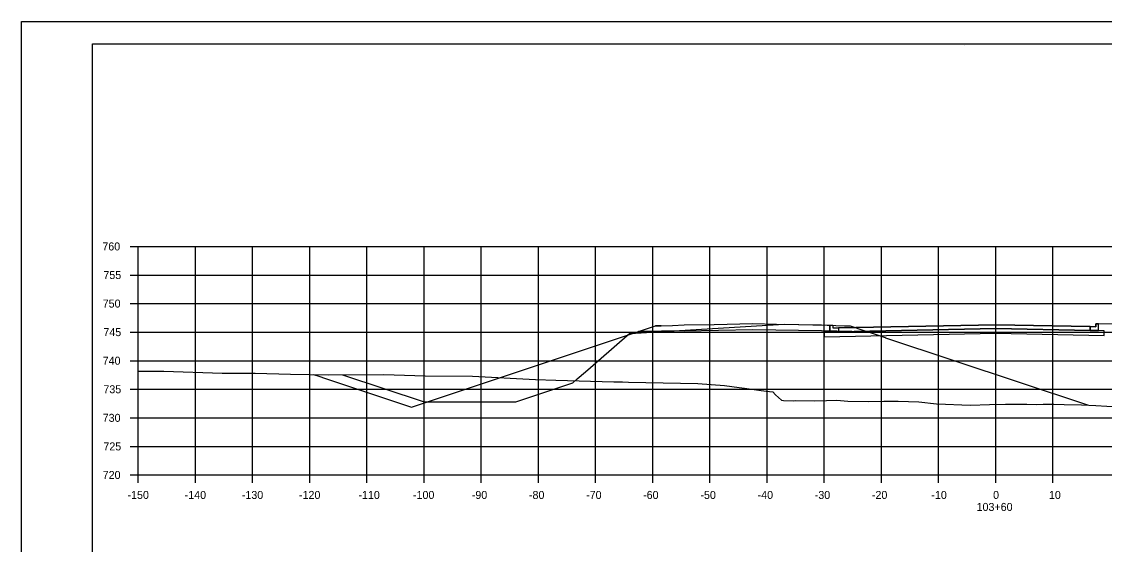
# Model space of a CAD drawing. Extents: x 1202951 to 1376887, y 378065 to 728038.
# Drawn here: x 1374114.6 to 1374304, y 379521.8 to 379613.3 of the extents above; entities that cross this region are included whole.
import ezdxf

# ---------------------------------------------------------------- set-up
doc = ezdxf.new("R2010")
doc.units = 0
for name, color, linetype in [('Default', 7, 'Continuous'), ('R_Alt Surface', 7, 'Continuous'), ('R_Axis', 7, 'Continuous'), ('R_Axis Annot', 7, 'Continuous'), ('R_Exist Surface', 7, 'Continuous'), ('R_Fin Surface', 7, 'Continuous'), ('R_Grid', 7, 'Continuous'), ('R_No Plot', 7, 'Continuous'), ('R_Proposed Road', 7, 'Continuous')]:
    doc.layers.add(name, color=color, linetype=linetype)

msp = doc.modelspace()

# ---------------------------------------------------------------- linework, layer by layer
at = {"layer": 'Default'}
for points in [[(1374255.98, 379560.17), (1374256.47, 379560.17), (1374256.48, 379559.67), (1374257.48, 379559.69), (1374257.48, 379559.02), (1374255.98, 379558.99)], [(1374302.98, 379560.39), (1374302.49, 379560.39), (1374302.48, 379559.89), (1374301.48, 379559.91), (1374301.48, 379559.24), (1374302.98, 379559.21)]]:
    msp.add_lwpolyline(points, close=True, dxfattribs=at)
at = {"layer": 'R_Alt Surface'}
for points in [[(1374255.98, 379560.17), (1374255.98, 379558.99), (1374257.48, 379559.02), (1374284.98, 379559.57), (1374301.48, 379559.24), (1374302.98, 379559.21), (1374302.98, 379560.39)], [(1374230.48, 379559.19), (1374222.48, 379559.03)], [(1374230.48, 379559.19), (1374242.49, 379559.43), (1374254.49, 379559.2)], [(1374254.49, 379559.2), (1374262.5, 379559.04)]]:
    msp.add_lwpolyline(points, dxfattribs=at)
for points in [[(1374257.48, 379559.69), (1374257.48, 379559.02), (1374284.98, 379559.57), (1374301.48, 379559.24), (1374301.48, 379559.91), (1374301.48, 379559.91), (1374284.98, 379560.24), (1374257.48, 379559.69)], [(1374284.98, 379559.57), (1374257.48, 379559.02), (1374255.98, 379558.99), (1374254.98, 379558.97), (1374254.98, 379558.14), (1374284.98, 379558.74), (1374303.98, 379558.36), (1374303.98, 379559.19), (1374302.98, 379559.21), (1374301.48, 379559.24)]]:
    msp.add_lwpolyline(points, close=True, dxfattribs=at)
at = {"layer": 'R_Axis'}
for p, q in [((1374133.58, 379573.94), (1374134.98, 379573.94)), ((1374134.98, 379533.94), (1374134.98, 379573.94)), ((1374133.58, 379568.94), (1374134.98, 379568.94)), ((1374133.58, 379563.94), (1374134.98, 379563.94)), ((1374133.58, 379558.94), (1374134.98, 379558.94)), ((1374133.58, 379553.94), (1374134.98, 379553.94)), ((1374133.58, 379548.94), (1374134.98, 379548.94)), ((1374133.58, 379543.94), (1374134.98, 379543.94)), ((1374133.58, 379538.94), (1374134.98, 379538.94)), ((1374133.58, 379533.94), (1374134.98, 379533.94)), ((1374134.98, 379533.94), (1374434.98, 379533.94)), ((1374134.98, 379532.54), (1374134.98, 379533.94)), ((1374144.98, 379532.54), (1374144.98, 379533.94)), ((1374154.98, 379532.54), (1374154.98, 379533.94)), ((1374164.98, 379532.54), (1374164.98, 379533.94)), ((1374174.98, 379532.54), (1374174.98, 379533.94)), ((1374184.98, 379532.54), (1374184.98, 379533.94)), ((1374194.98, 379532.54), (1374194.98, 379533.94)), ((1374204.98, 379532.54), (1374204.98, 379533.94)), ((1374214.98, 379532.54), (1374214.98, 379533.94)), ((1374224.98, 379532.54), (1374224.98, 379533.94)), ((1374234.98, 379532.54), (1374234.98, 379533.94)), ((1374244.98, 379532.54), (1374244.98, 379533.94)), ((1374254.98, 379532.54), (1374254.98, 379533.94)), ((1374264.98, 379532.54), (1374264.98, 379533.94)), ((1374274.98, 379532.54), (1374274.98, 379533.94)), ((1374284.98, 379532.54), (1374284.98, 379533.94)), ((1374294.98, 379532.54), (1374294.98, 379533.94))]:
    msp.add_line(p, q, dxfattribs=at)
at = {"layer": 'R_Exist Surface'}
msp.add_lwpolyline([(1374134.98, 379552.09), (1374139.42, 379552.09), (1374149.67, 379551.78), (1374155.41, 379551.76), (1374161.58, 379551.61), (1374168.28, 379551.48), (1374177.94, 379551.52), (1374185.14, 379551.3), (1374193.45, 379551.23), (1374204.45, 379550.64), (1374208, 379550.51), (1374218.15, 379550.25), (1374219.67, 379550.22), (1374220.74, 379550.19), (1374232.87, 379549.94), (1374237.53, 379549.61), (1374240.1, 379549.27), (1374241.03, 379549.12), (1374241.86, 379549.02), (1374244.8, 379548.62), (1374246.01, 379548.48), (1374246.47, 379547.96), (1374247.48, 379547.03), (1374247.87, 379546.97), (1374249.64, 379546.9), (1374250, 379546.95), (1374253.32, 379546.94), (1374255.37, 379546.97), (1374257.21, 379547.01), (1374259.13, 379546.86), (1374262.71, 379546.82), (1374265.4, 379546.86), (1374267.89, 379546.88), (1374271.51, 379546.72), (1374274.6, 379546.39), (1374276.18, 379546.34), (1374279.04, 379546.23), (1374280.59, 379546.16), (1374283.87, 379546.25), (1374286.69, 379546.35), (1374290.44, 379546.35), (1374292.08, 379546.26), (1374293.27, 379546.35), (1374295.12, 379546.35), (1374296.94, 379546.26), (1374299.96, 379546.19), (1374302.47, 379546.08), (1374308.28, 379545.77)], dxfattribs=at)
at = {"layer": 'R_Fin Surface'}
for points in [[(1374165.61, 379551.53), (1374166.75, 379551.15), (1374167.56, 379550.88), (1374182.8, 379545.8), (1374194.16, 379549.59), (1374222.48, 379559.03), (1374223.91, 379559.51), (1374225.48, 379560.03), (1374225.99, 379560.03), (1374226.48, 379560.03), (1374228.45, 379560.11), (1374230.48, 379560.19), (1374235.74, 379560.3), (1374242.49, 379560.43), (1374246.61, 379560.35), (1374254.49, 379560.2), (1374255.51, 379560.16), (1374258.5, 379560.04), (1374258.72, 379560.04), (1374259.5, 379560.04), (1374261.93, 379559.23), (1374262.5, 379559.04), (1374265.62, 379558), (1374265.72, 379557.97), (1374301.03, 379546.23), (1374301.29, 379546.13)], [(1374170.71, 379551.49), (1374184.98, 379546.74), (1374193.84, 379546.74), (1374196.11, 379546.74), (1374197.54, 379546.74), (1374199.8, 379546.74), (1374201.03, 379546.74), (1374211.02, 379550.08), (1374211.78, 379550.75), (1374213.2, 379551.97), (1374214.09, 379552.75), (1374215.49, 379553.97), (1374220.98, 379558.74), (1374221.98, 379558.74), (1374247.98, 379560.33), (1374252.98, 379560.23), (1374255.98, 379560.17), (1374256.47, 379560.17), (1374256.48, 379559.67), (1374257.48, 379559.69), (1374284.98, 379560.24), (1374301.48, 379559.91), (1374302.48, 379559.89), (1374302.49, 379560.39), (1374302.98, 379560.39), (1374305.98, 379560.45)]]:
    msp.add_lwpolyline(points, dxfattribs=at)
at = {"layer": 'R_Grid'}
for p, q in [((1374134.98, 379573.94), (1374434.98, 379573.94)), ((1374134.98, 379533.94), (1374134.98, 379573.94)), ((1374144.98, 379533.94), (1374144.98, 379573.94)), ((1374154.98, 379533.94), (1374154.98, 379573.94)), ((1374164.98, 379533.94), (1374164.98, 379573.94)), ((1374174.98, 379533.94), (1374174.98, 379573.94)), ((1374184.98, 379533.94), (1374184.98, 379573.94)), ((1374194.98, 379533.94), (1374194.98, 379573.94)), ((1374204.98, 379533.94), (1374204.98, 379573.94)), ((1374214.98, 379533.94), (1374214.98, 379573.94)), ((1374224.98, 379533.94), (1374224.98, 379573.94)), ((1374234.98, 379533.94), (1374234.98, 379573.94)), ((1374244.98, 379533.94), (1374244.98, 379573.94)), ((1374254.98, 379533.94), (1374254.98, 379573.94)), ((1374264.98, 379533.94), (1374264.98, 379573.94)), ((1374274.98, 379533.94), (1374274.98, 379573.94)), ((1374284.98, 379533.94), (1374284.98, 379573.94)), ((1374294.98, 379533.94), (1374294.98, 379573.94)), ((1374134.98, 379568.94), (1374434.98, 379568.94)), ((1374134.98, 379563.94), (1374434.98, 379563.94)), ((1374134.98, 379558.94), (1374434.98, 379558.94)), ((1374134.98, 379553.94), (1374434.98, 379553.94)), ((1374134.98, 379548.94), (1374434.98, 379548.94)), ((1374134.98, 379543.94), (1374434.98, 379543.94)), ((1374134.98, 379538.94), (1374434.98, 379538.94)), ((1374134.98, 379533.94), (1374434.98, 379533.94))]:
    msp.add_line(p, q, dxfattribs=at)
at = {"layer": 'R_No Plot'}
for p, q in [((1374114.58, 379613.29), (1374447.91, 379613.29)), ((1374126.98, 379609.4), (1374443.16, 379609.4)), ((1374126.98, 379403.94), (1374126.98, 379609.4)), ((1374279.5, 379609.14), (1374279.5, 379609.14)), ((1374279.5, 379609.14), (1374279.5, 379609.14))]:
    msp.add_line(p, q, dxfattribs=at)
for points in [[(1374114.57, 379613.29), (1374447.91, 379613.29), (1374447.91, 379399.95), (1374114.57, 379399.95)], [(1374360.9, 379609.4), (1374380.52, 379609.4), (1374380.52, 379599.52), (1374396.63, 379599.52), (1374419.83, 379599.52), (1374419.83, 379575.18), (1374443.16, 379575.18), (1374443.16, 379403.94), (1374126.98, 379403.94), (1374126.98, 379609.4)]]:
    msp.add_lwpolyline(points, close=True, dxfattribs=at)
at = {"layer": 'R_Proposed Road'}
for points in [[(1374226.48, 379560.03), (1374225.48, 379560.03)], [(1374258.5, 379560.04), (1374259.5, 379560.04)]]:
    msp.add_lwpolyline(points, dxfattribs=at)

# ---------------------------------------------------------------- texts
at = {"layer": 'R_Axis Annot'}
for s, p in [('760', (1374128.69, 379573.24)), ('755', (1374128.87, 379568.24)), ('750', (1374128.75, 379563.24)), ('745', (1374128.87, 379558.24)), ('740', (1374128.75, 379553.24)), ('735', (1374128.87, 379548.24)), ('730', (1374128.75, 379543.24)), ('725', (1374128.87, 379538.24)), ('720', (1374128.75, 379533.24)), ('-150', (1374133.09, 379529.74)), ('-140', (1374143.09, 379529.74)), ('-130', (1374153.09, 379529.74)), ('-120', (1374163.09, 379529.74)), ('-110', (1374173.49, 379529.74)), ('-100', (1374183.03, 379529.74)), ('-90', (1374193.32, 379529.74)), ('-80', (1374203.32, 379529.74)), ('-70', (1374213.32, 379529.74)), ('-60', (1374223.29, 379529.74)), ('-50', (1374233.32, 379529.74)), ('-40', (1374243.32, 379529.74)), ('-30', (1374253.32, 379529.74)), ('-20', (1374263.32, 379529.74)), ('-10', (1374273.72, 379529.74)), ('0', (1374284.52, 379529.74)), ('10', (1374294.29, 379529.74)), ('103+60', (1374281.63, 379527.64))]:
    msp.add_text(s, height=1.4, dxfattribs=at).set_placement(p)

doc.saveas('drawing.dxf')
